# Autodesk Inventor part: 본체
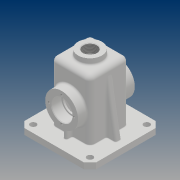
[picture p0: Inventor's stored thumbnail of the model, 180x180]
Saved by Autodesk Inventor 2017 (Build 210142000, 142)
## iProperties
Part Number: 본체
Material: 일반
Document SubType Name: Modeling
Designer: 20
Density: 1 g/cm^3
Appearance: 기본값
Mass: 292.705 g
Surface Area: 898.371 cm^2
Volume: 292.705 cm^3
Author: 20
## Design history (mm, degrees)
sketch "스케치1"
  geometry: L1 (-32.5, -32.5)-(32.5, -32.5); L2 (32.5, -32.5)-(32.5, 32.5); L3 (32.5, 32.5)-(-32.5, 32.5); L4 (-32.5, 32.5)-(-32.5, -32.5); L5 (-32.5, -32.5)-(32.5, 32.5); L6 (32.5, -32.5)-(-32.5, 32.5); 1 further point
  constraints: 12 end point, 2 midpoint, 2 parallel, 1 horizontal, 1 perpendicular
  dimensions: "d0" = 65 distance of L3.end L2.end; "d1" = 65 distance of L2.end L1.end
extrude "돌출1" new body sketch "스케치1" distance "d2" = 110; taper "d3" = 0 deg
fillet "모깎기1" dims "d4" = 8
feature "쉘1" dims "d5" = 5
node "작업 평면1"
sketch "스케치2"
  geometry: C1 r 20 at (0, 0); 1 further point
  constraints: 1 centre point, 1 coincident
  dimensions: "d7" = 40 diameter of C1
extrude "돌출2" join sketch "스케치2" stored distance "d8" = 110; taper "d9" = 0 deg
hole "구멍1" diameter "d12" = 22.835; stored, may be unused: countersink angle "d16" = 90 deg, drill point angle "d18" = 118 deg; dims "d10" = 10, "d11" = 10, "d13" = 50, "d14" = 4, "d15" = 2, "d17" = 59.3
node "작업 평면2"
sketch "스케치3"
  geometry: L1 (-27.5, -24.5)-(-27.5, 24.5) reference; L2 (24.5, -27.5)-(-24.5, -27.5) reference; L3 (27.5, 24.5)-(27.5, -24.5) reference; L4 (-24.5, 27.5)-(24.5, 27.5) reference; L5 (60, -60)-(-60, -60); L6 (-60, -60)-(-60, 60); L7 (-60, 60)-(60, 60); L8 (60, 60)-(60, -60); L9 (60, -60)-(-60, 60); L10 (-60, -60)-(60, 60); A1 r 3 centre (-24.5, -24.5) between (-27.5, -24.5) and (-24.5, -27.5) reference; A2 r 3 centre (24.5, -24.5) between (24.5, -27.5) and (27.5, -24.5) reference; A3 r 3 centre (24.5, 24.5) between (27.5, 24.5) and (24.5, 27.5) reference; A4 r 3 centre (-24.5, 24.5) between (-24.5, 27.5) and (-27.5, 24.5) reference; 1 further point
  constraints: 12 end point, 2 midpoint, 2 parallel, 1 horizontal, 1 perpendicular
  dimensions: "d20" = 120 distance of L6.end L7.end; "d21" = 120 distance of L5.end L6.end
extrude "돌출3" join sketch "스케치3" distance "d22" = 10; taper "d23" = 0 deg
sketch "스케치4"
  geometry: L1 (-60, 10)-(60, 10) reference; L2 (-48, 10)-(-42.625, 40.485); L3 (-60, 10)-(-60, 0) reference; 1 further point
  constraints: 2 end point, 1 point on line
  dimensions: "d24" = 10 deg angle of L3 L2; "d25" = 12 distance from line of L3 L2.start
feature "리브1" sketch "스케치4" dims "d26" = 1, "d27" = 10, "d28" = 0, "d29" = 0, "d30" = 1, "d31" = 1
node "작업 평면3"
sketch "스케치6"
  geometry: L1 (84.5, -102)-(-35.5, -102) reference; C1 r 27.5 at (24.5, -47); 2 further points
  constraints: 1 centre point, 1 midpoint, 1 vertical alignment
  dimensions: "d35" = 55 diameter of C1; "d36" = 55 distance from line of L1 C1.centre
extrude "돌출4" join sketch "스케치6" stored distance "d37" = 15; taper "d38" = 0 deg
sketch "스케치7"
  geometry: L1 (-47.5, 27.5)-(-47.5, 82.5) reference; L2 (-47.5, 55)-(41.269, 55); L3 (-47.5, 72.5)-(-30.5, 72.5); L4 (-30.5, 72.5)-(-30.5, 70); L5 (-30.5, 70)-(-27.5, 70); L6 (-27.5, 0)-(-27.5, 102) reference; L7 (-47.5, 72.5)-(-47.5, 55); L8 (-27.5, 70)-(-27.5, 55); 1 further point
  constraints: 12 end point, 3 horizontal, 3 point on line, 3 vertical, 1 midpoint
  dimensions: "d39" = 17 distance of L3.start L3.end; "d40" = 35 diameter of L3 L2; "d41" = 30 diameter of L5 L2
revolve "회전1" sketch "스케치7" stored, may be unused: angle "d42" = 90 deg
sketch "스케치8" dims "d43" = 42
  geometry: L1 (0, 0)-(0, 21); C1 r 17.5 at (0, 0) reference; 3 further points
  constraints: 2 coincident, 2 end point, 1 vertical, 1 vertical alignment, 2 other
hole "구멍2" sketch "스케치8" at (0, 21) diameter "d44" = 3.242; stored, may be unused: countersink angle "d48" = 90 deg, drill point angle "d50" = 118 deg; dims "d45" = 8, "d46" = 4, "d47" = 2, "d49" = 10
sketch "스케치9"
  geometry: L1 (60, 10)-(-60, 10) reference; L2 (-42.5, 10)-(-42.5, 23.769); L3 (-32.5, 10)-(-32.5, 42.51) reference; L4 (-27.5, 0)-(-27.5, 102) reference; 1 further point
  constraints: 2 end point, 1 point on line, 1 vertical
  dimensions: "d55" = 15 distance between parallel lines of L2 L4
feature "리브2" sketch "스케치9" dims "d56" = 1, "d57" = 6, "d58" = 0, "d59" = 0, "d60" = 1, "d61" = 1
sketch "스케치10"
  geometry: L1 (-60, 60)-(-60, -60) reference; L2 (60, 60)-(-60, 60) reference; C1 r 5 at (-47.5, 47.5); 1 further point
  constraints: 1 centre point
  dimensions: "d62" = 10 diameter of C1; "d63" = 12.5 distance from line of L1 C1.centre; "d64" = 12.5 distance from line of L2 C1.centre
extrude "돌출5" cut sketch "스케치10" distance "d65" = 10; taper "d66" = 0 deg
chamfer "모따기1" distance "d73" = 10; stored, may be unused: second distance "d74" = 2, angle "d75" = 45 deg
fillet "모깎기2" dims "d76" = 3
fillet "모깎기3" dims "d77" = 3
fillet "모깎기4" dims "d78" = 1
fillet "모깎기5" dims "d79" = 3
chamfer "모따기2" distance "d80" = 1; stored, may be unused: second distance "d81" = 2, angle "d82" = 45 deg
fillet "모깎기6" dims "d83" = 0.3
node "작업 평면4"
sketch "스케치11"
  geometry: L1 (57, 0)-(57, 91) reference; L2 (44.5, -18)-(4.5, -18) reference; 2 further points
  constraints: 1 other
  dimensions: "d85" = 32.5 distance from line of L1 point (24.5, 8); "d86" = 26 distance from line of point (24.5, 8) L2
feature "엠보싱1" sketch "스케치11" dims "d0" = 65, "d1" = 65, "d87" = 0.5, "d88" = 0
node "솔리드1"
mirror "미러1"
pattern_circular "원형 패턴1" dims angle "d52" = 360 deg
mirror "미러2"
pattern_linear "직사각형 패턴1" dims "d69" = 95, "d72" = -95
other parameters: "d34" = 15, "d84" = 72.75
